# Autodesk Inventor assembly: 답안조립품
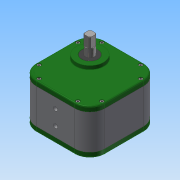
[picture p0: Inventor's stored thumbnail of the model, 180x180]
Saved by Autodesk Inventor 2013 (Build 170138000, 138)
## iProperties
Created: 2017-11
Part Number: 답안조립품
Document SubType Name: Assembly
Designer: Administrator
Author: Administrator
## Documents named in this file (11)
- C:\Users\Administrator\Desktop\371108V1010\답안조립품.iam
- C:\Users\Administrator\Desktop\371108V1010\본체.ipt
- C:\Users\Administrator\Desktop\371108V1010\뒤커버.ipt
- C:\Users\Administrator\Desktop\371108V1010\메인축.ipt
- C:\Users\Administrator\Desktop\371108V1010\베어링 608.ipt
- C:\Users\Administrator\Desktop\371108V1010\베어링 6003.ipt
- C:\Users\Administrator\Desktop\371108V1010\볼트 M4.ipt
- C:\Users\Administrator\Desktop\371108V1010\서브축.ipt
- C:\Users\Administrator\Desktop\371108V1010\앞커버.ipt
- C:\Users\Administrator\Desktop\371108V1010\오일실 8 22 7.ipt
- C:\Users\Administrator\Desktop\371108V1010\오일실 17 32 8.ipt
